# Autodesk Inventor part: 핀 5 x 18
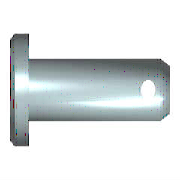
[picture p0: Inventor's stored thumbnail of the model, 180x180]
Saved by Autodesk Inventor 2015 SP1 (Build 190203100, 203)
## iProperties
Created: 2012-02
Part Number: 핀 5 x 18
Material: 강철
Description: 머리가 있는 클레비스 핀
Document SubType Name: Modeling
Standard: ISO 2341
Designer: test
Standard Revision: Second edition 1986-11-01
Standards Organization: ISO
Language: ko-KR
Size Designation: B - 5 x 18
Categories: <MemberInstance><Categories><Category DisplayName="조임쇠" InternalName="e4da775c-781d-43d5-af7c-5136215cf5a6" Mnemonic="FSTN"><Category DisplayName="핀" InternalNa
Density: 7.85 g/cm^3
Appearance: 강철
IsCustomPart: 1
Author: test
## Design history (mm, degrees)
sketch "스케치1"
  geometry: L1 (-1.6, 0)-(-1.6, 4); L2 (-1.6, 4)-(0, 4); L3 (0, 4)-(0, 2.5); L4 (0, 2.5)-(18, 2.5); L5 (18, 2.5)-(18, 0); L6 (-1.6, 0)-(18, 0); L7 (-4, 0)-(17, 0) reference; L8 (0, -0.98)-(0, 3.08) reference; C1 r 0.6 at (15.1, 0)
  constraints: 12 end point, 3 parallel, 2 collinear, 2 perpendicular, 1 centre point, 1 point on line, 1 vertical
  dimensions: "d0" = 5 diameter of L4 L6 (= NND); "d1" = 8 diameter of L2 L6 (= KOD); "d2" = 1.6 distance of L1.end L2.end (= KOH); "d3" = 18 distance of L3.end L4.end (= NLG); "d5" = 2.9 distance from line of L5 C1.centre (= DIST); "d6" = 1.2 diameter of C1 (= BOR)
revolve "본체" stored, may be unused: angle "d4" = 90 deg
extrude "구멍" cut sketch "스케치1" stored distance "d7" = 5 (= NND); taper "d8" = 0 deg
workaxis "Work Axis1"
workplane "Work Plane1"
body "Solid1"
chamfer "모따기1" distance "d9" = 1 (= PHH2); stored, may be unused: angle "d10" = 45 deg (= FAWI2), second distance "d16" = 1 (= PHH2)
chamfer "모따기2" distance "d11" = 2 (= PHH1); stored, may be unused: angle "d12" = 30 deg (= FAWI1), second distance "d17" = 2 (= PHH1)
other parameters: "PHH1" = 2 [user parameter; used in 2 equation terms], "PHH2" = 1 [user parameter; used in 2 equation terms], "KOD" = 8 [user parameter; used in 1 equation term], "KOH" = 1.6 [user parameter; used in 1 equation term], "NND" = 5 [user parameter; used in 2 equation terms], "FAWI1" = 30 deg [user parameter; used in 1 equation term], "FAWI2" = 45 deg [user parameter; used in 1 equation term], "DIST" = 2.9 [user parameter; used in 1 equation term], "BOR" = 1.2 [user parameter; used in 1 equation term], "NLG" = 18 [user parameter; used in 1 equation term], "d13" = 0, "d14" = 0, "d27" = 0, "d28" = 0, "d29" = 0, "d30" = 0, "d31" = 0
